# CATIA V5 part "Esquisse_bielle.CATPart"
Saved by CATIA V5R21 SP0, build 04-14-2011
Part number: Part3
Bounding box of the stored display mesh (mm): x 0 to 0, y -20.75 to 20.75, z -3.5 to 3.5
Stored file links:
  C:\Users\Olivier\Desktop\redaction TBM CATIA\CATIA\DONNEES\Exercice esquisse (projet)\Exercice esquisse 1(projet).CATPart
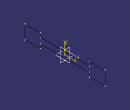
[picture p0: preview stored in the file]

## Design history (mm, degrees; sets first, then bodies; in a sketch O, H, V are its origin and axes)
Body1 (main body)
  Sketch1 on yz-plane, origin (0, 0, 0), H (0, 1, 0), V (0, 0, 1)
    line L1 (-20.75, -3.5) -> (-12.75, -3.5)
    line L2 (-12.75, -3.5) -> (-12.75, -1.5)
    line L3 (-12.75, -1.5) -> (12.75, -1.5)
    line L4 (12.75, -1.5) -> (12.75, -3.5)
    point P5 (12.75, -3.5)
    line L5 (12.75, -3.5) -> (20.75, -3.5)
    line L6 (20.75, -3.5) -> (20.75, 3.5)
    line L7 (20.75, 3.5) -> (12.75, 3.5)
    point P8 (12.75, 3.5)
    line L8 (12.75, 3.5) -> (12.75, 1.5)
    line L9 (12.75, 1.5) -> (-12.75, 1.5)
    point P10 (-12.75, 1.5)
    line L10 (-12.75, 1.5) -> (-12.75, 3.5)
    point P11 (-12.75, 3.5)
    line L11 (-12.75, 3.5) -> (-20.75, 3.5)
    line L12 (-20.75, 3.5) -> (-20.75, -3.5)
    distance L12 L6 = 41.5
    length L11 = 8
    length L7 = 8
    distance L9 L3 = 3
    length L6 = 7
    length L4 = 2
    horizontal: L1 H, L3 H, L5 H, L7 H, L9 H, L11 H
    vertical: L2 V, L4 V, L6 V, L8 V, L10 V, L12 V
    coincidence: P5 L1, P8 L4, P10 L2, P11 L7
    symmetry: L6 L12 V, L9 L3 H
